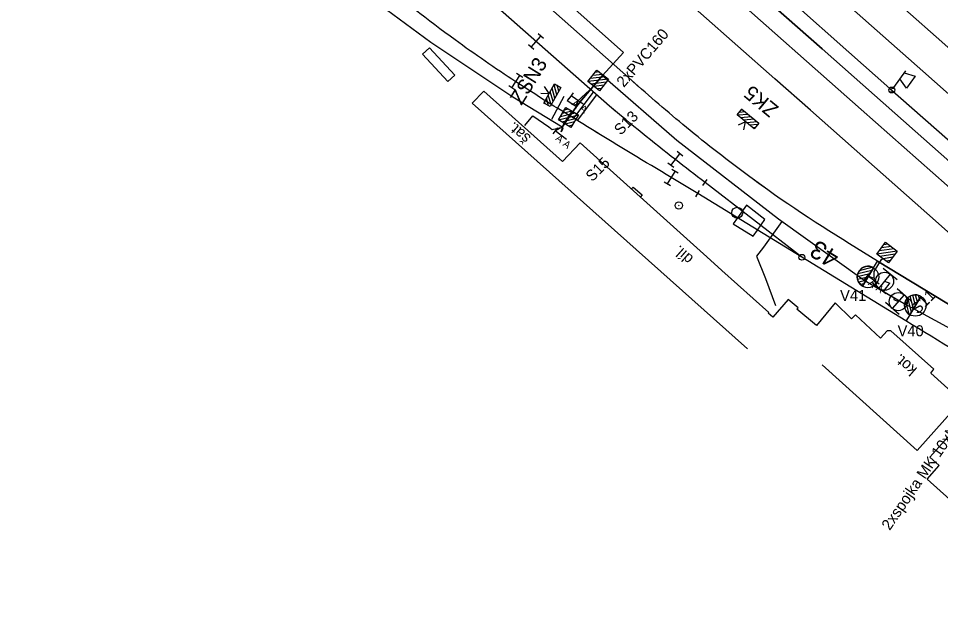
# Model space of a CAD drawing. Extents: x -496570 to -495506, y -1089156 to -1088046.
# Drawn here: x -496392.9 to -496267.2, y -1088434 to -1088354.3 of the extents above; entities that cross this region are included whole.
import ezdxf

# ---------------------------------------------------------------- set-up
doc = ezdxf.new("R2010")
doc.units = 0
for name, color, linetype in [('11', 7, 'Continuous'), ('14', 7, 'Continuous'), ('15', 7, 'Continuous'), ('20', 7, 'Continuous'), ('27', 7, 'Continuous'), ('39', 7, 'Continuous'), ('49', 7, 'Continuous'), ('54', 7, 'Continuous'), ('PŘÍSTUPOVÉ_CESTY', 7, 'Continuous'), ('PŮVODNÍ_NÁVRH', 7, 'Continuous'), ('SEE', 7, 'Continuous')]:
    doc.layers.add(name, color=color, linetype=linetype)

msp = doc.modelspace()

# ---------------------------------------------------------------- linework, layer by layer
at = {"layer": '11'}
for p, q in [((-496317.221, -1088367.889), (-496314.545, -1088364.306)), ((-496316.708, -1088368.205), (-496314.093, -1088364.705)), ((-496302.846, -1088379.821), (-496302.92, -1088379.755))]:
    msp.add_line(p, q, dxfattribs=at)
for centre, radius in [((-496302.883, -1088379.788), 0.5), ((-496294.929, -1088380.778), 0.75)]:
    msp.add_circle(centre, radius, dxfattribs=at)
at = {"layer": '14'}
for points in [[(-496500.326, -1088150.883), (-496478.319, -1088170.391), (-496459.205, -1088187.309), (-496440.603, -1088203.768), (-496419.398, -1088222.532), (-496401.337, -1088238.524), (-496381.863, -1088255.763), (-496363.496, -1088272.022), (-496344.908, -1088288.479), (-496325.602, -1088305.577), (-496305.115, -1088323.698), (-496285.279, -1088341.274), (-496267.778, -1088356.78), (-496248.642, -1088373.733), (-496220.391, -1088398.759), (-496201.351, -1088415.62), (-496182.974, -1088431.889), (-496164.259, -1088448.462), (-496145.687, -1088464.902), (-496132.984, -1088476.226), (-496115.09, -1088492.058), (-496092.682, -1088511.89), (-496073.961, -1088528.378)], [(-496111.45, -1088501.61), (-496112.796, -1088500.414), (-496116.847, -1088496.777), (-496137.726, -1088478.277), (-496158.004, -1088460.314), (-496179.39, -1088441.364), (-496198.571, -1088424.361), (-496223.52, -1088402.267), (-496247.329, -1088381.198), (-496269.626, -1088361.454), (-496288.304, -1088344.927), (-496319.947, -1088316.905), (-496344.485, -1088295.207), (-496348.139, -1088291.966), (-496366.841, -1088275.405), (-496385.169, -1088259.187), (-496404.395, -1088242.153), (-496422.154, -1088226.434), (-496443.818, -1088207.26), (-496462.548, -1088190.678), (-496481.576, -1088173.849), (-496503.417, -1088154.088)], [(-496465.102, -1088201.03), (-496456.086, -1088209.031), (-496439.8, -1088223.453), (-496418.031, -1088242.716), (-496400.164, -1088258.552), (-496382.525, -1088274.174), (-496378.001, -1088278.141), (-496364.605, -1088290.03), (-496358.266, -1088295.605), (-496338.75, -1088312.899), (-496318.462, -1088330.866), (-496297.237, -1088349.647), (-496278.02, -1088366.672), (-496252.626, -1088389.158), (-496233.92, -1088405.779), (-496222.755, -1088415.674), (-496210.969, -1088426.126), (-496208.778, -1088428.033)], [(-496238.055, -1088408.352), (-496252.739, -1088395.349), (-496269.088, -1088380.829), (-496284.933, -1088366.798), (-496289.774, -1088362.518), (-496304.914, -1088349.103), (-496331.751, -1088325.354), (-496382.404, -1088280.635)], [(-496312.364, -1088366.234), (-496339.426, -1088342.308), (-496363.327, -1088321.131), (-496384.97, -1088301.986), (-496397.177, -1088291.214)], [(-496309.356, -1088362.702), (-496336.13, -1088338.96), (-496360.078, -1088317.72), (-496381.817, -1088298.451), (-496389.608, -1088291.56)], [(-496286.111, -1088386.854), (-496299.315, -1088376.648)], [(-496271.935, -1088395.519), (-496286.111, -1088386.854), (-496300.313, -1088378.173)], [(-496225.685, -1088419.311), (-496239.228, -1088409.789), (-496247.333, -1088404.627), (-496261.601, -1088395.991), (-496275.815, -1088387.388)]]:
    msp.add_lwpolyline(points, dxfattribs=at)
for points in [[(-496300.313, -1088378.173), (-496303.924, -1088375.986), (-496314.684, -1088369.445), (-496325.128, -1088362.908), (-496333.397, -1088357.203), (-496344.314, -1088348.841)], [(-496275.815, -1088387.388), (-496290.743, -1088377.667), (-496293.191, -1088375.882), (-496301.865, -1088369.14), (-496309.356, -1088362.702)], [(-496299.315, -1088376.648), (-496303.364, -1088373.532), (-496312.364, -1088366.234)], [(-496239.518, -1088416.014), (-496251.238, -1088408.214), (-496258.061, -1088403.984), (-496271.935, -1088395.519)]]:
    msp.add_spline(points, degree=3, dxfattribs=at)
at = {"layer": '15'}
for p, q in [((-496321.328, -1088357.025), (-496322.076, -1088356.362)), ((-496323.028, -1088358.191), (-496321.702, -1088356.693)), ((-496322.654, -1088358.522), (-496323.402, -1088357.859)), ((-496325.667, -1088363.751), (-496324.589, -1088362.065)), ((-496324.168, -1088362.335), (-496325.01, -1088361.796)), ((-496312.479, -1088362.554), (-496315.287, -1088362.893)), ((-496312.896, -1088362.227), (-496314.96, -1088362.476)), ((-496313.313, -1088361.899), (-496314.632, -1088362.058)), ((-496313.73, -1088361.572), (-496314.305, -1088361.641)), ((-496325.246, -1088364.02), (-496326.088, -1088363.481)), ((-496312.806, -1088362.971), (-496314.87, -1088363.22)), ((-496313.134, -1088363.389), (-496314.452, -1088363.548)), ((-496313.461, -1088363.806), (-496314.035, -1088363.875)), ((-496319.315, -1088368.123), (-496316.572, -1088367.433)), ((-496319.043, -1088367.669), (-496317.027, -1088367.161)), ((-496318.77, -1088367.213), (-496317.482, -1088366.889)), ((-496318.498, -1088366.758), (-496317.937, -1088366.617)), ((-496318.86, -1088368.395), (-496316.844, -1088367.888)), ((-496318.404, -1088368.668), (-496317.116, -1088368.344)), ((-496317.949, -1088368.94), (-496317.388, -1088368.799)), ((-496302.352, -1088373.057), (-496303.136, -1088372.437)), ((-496303.984, -1088374.316), (-496302.744, -1088372.748)), ((-496304.439, -1088376.843), (-496303.409, -1088375.129)), ((-496303.592, -1088374.627), (-496304.376, -1088374.007)), ((-496302.981, -1088375.387), (-496303.837, -1088374.871)), ((-496304.011, -1088377.101), (-496304.867, -1088376.585)), ((-496274.369, -1088385.053), (-496274.942, -1088385.137)), ((-496273.093, -1088386.003), (-496275.892, -1088386.413)), ((-496273.518, -1088385.687), (-496275.575, -1088385.988)), ((-496273.41, -1088386.429), (-496275.467, -1088386.729)), ((-496273.944, -1088385.37), (-496275.258, -1088385.562)), ((-496273.727, -1088386.854), (-496275.041, -1088387.046)), ((-496274.044, -1088387.279), (-496274.616, -1088387.363)), ((-496273.098, -1088389.923), (-496275.017, -1088388.378)), ((-496274.643, -1088391.842), (-496276.562, -1088390.297)), ((-496274.058, -1088389.15), (-496275.602, -1088391.07)), ((-496271.232, -1088392.777), (-496273.093, -1088391.162)), ((-496272.162, -1088391.97), (-496273.778, -1088393.83)), ((-496272.847, -1088394.638), (-496274.708, -1088393.023))]:
    msp.add_line(p, q, dxfattribs=at)
for points in [[(-496313.713, -1088364.127), (-496315.287, -1088362.893), (-496314.052, -1088361.319), (-496312.479, -1088362.554)], [(-496313.713, -1088364.127), (-496315.287, -1088362.893), (-496314.052, -1088361.319), (-496312.479, -1088362.554)], [(-496318.288, -1088366.407), (-496316.572, -1088367.433), (-496317.598, -1088369.15), (-496319.315, -1088368.123)], [(-496318.288, -1088366.407), (-496316.572, -1088367.433), (-496317.598, -1088369.15), (-496319.315, -1088368.123)], [(-496274.288, -1088387.607), (-496275.892, -1088386.413), (-496274.697, -1088384.809), (-496273.093, -1088386.003)], [(-496274.288, -1088387.607), (-496275.892, -1088386.413), (-496274.697, -1088384.809), (-496273.093, -1088386.003)]]:
    msp.add_lwpolyline(points, close=True, dxfattribs=at)
for points in [[(-496313.713, -1088364.127), (-496315.287, -1088362.893), (-496314.052, -1088361.319), (-496312.479, -1088362.554), (-496313.713, -1088364.127)], [(-496313.713, -1088364.127), (-496315.287, -1088362.893), (-496314.052, -1088361.319), (-496312.479, -1088362.554), (-496313.713, -1088364.127)], [(-496318.288, -1088366.407), (-496316.572, -1088367.433), (-496317.598, -1088369.15), (-496319.315, -1088368.123), (-496318.288, -1088366.407)], [(-496318.288, -1088366.407), (-496316.572, -1088367.433), (-496317.598, -1088369.15), (-496319.315, -1088368.123), (-496318.288, -1088366.407)], [(-496274.288, -1088387.607), (-496275.892, -1088386.413), (-496274.697, -1088384.809), (-496273.093, -1088386.003), (-496274.288, -1088387.607)], [(-496274.288, -1088387.607), (-496275.892, -1088386.413), (-496274.697, -1088384.809), (-496273.093, -1088386.003), (-496274.288, -1088387.607)]]:
    msp.add_lwpolyline(points, dxfattribs=at)
for centre in [(-496274.832, -1088390.115), (-496272.972, -1088392.905)]:
    msp.add_circle(centre, 1.232, dxfattribs=at)
at = {"layer": '20'}
for p, q in [((-496317.297, -1088364.43), (-496317.867, -1088365.252)), ((-496315.955, -1088365.97), (-496317.582, -1088364.841)), ((-496319.451, -1088369.2), (-496320.063, -1088369.99)), ((-496318.191, -1088370.806), (-496319.757, -1088369.595)), ((-496276.892, -1088388.957), (-496277.462, -1088389.779)), ((-496275.55, -1088390.497), (-496277.177, -1088389.368))]:
    msp.add_line(p, q, dxfattribs=at)
at = {"layer": '27'}
for p, q in [((-496299.62, -1088377.044), (-496299.01, -1088376.252)), ((-496300.574, -1088378.599), (-496300.052, -1088377.747)), ((-496276.34, -1088388.272), (-496275.815, -1088387.388)), ((-496276.557, -1088388.638), (-496278.495, -1088389.128)), ((-496276.441, -1088388.222), (-496278.281, -1088388.687)), ((-496277.84, -1088390.786), (-496276.341, -1088388.272)), ((-496276.34, -1088388.273), (-496277.84, -1088390.786)), ((-496276.341, -1088388.272), (-496276.34, -1088388.273)), ((-496276.828, -1088389.093), (-496278.552, -1088389.528)), ((-496277.101, -1088389.549), (-496278.502, -1088389.903)), ((-496277.374, -1088390.004), (-496278.357, -1088390.253)), ((-496277.645, -1088390.46), (-496278.108, -1088390.577)), ((-496271.493, -1088394.623), (-496271.949, -1088392.78)), ((-496271.181, -1088394.324), (-496271.66, -1088392.384)), ((-496269.888, -1088392.182), (-496271.402, -1088394.687)), ((-496271.401, -1088394.688), (-496269.888, -1088392.182)), ((-496270.907, -1088393.87), (-496271.333, -1088392.145)), ((-496270.633, -1088393.415), (-496270.98, -1088392.013)), ((-496270.359, -1088392.962), (-496270.603, -1088391.975)), ((-496270.084, -1088392.507), (-496270.199, -1088392.044)), ((-496271.401, -1088394.688), (-496271.935, -1088395.567)), ((-496271.402, -1088394.687), (-496271.401, -1088394.688))]:
    msp.add_line(p, q, dxfattribs=at)
for points in [[(-496286.111, -1088386.854), (-496299.315, -1088376.648)], [(-496271.935, -1088395.519), (-496286.111, -1088386.854), (-496300.313, -1088378.173)], [(-496275.815, -1088387.388), (-496261.601, -1088395.991), (-496247.333, -1088404.627)]]:
    msp.add_lwpolyline(points, dxfattribs=at)
for centre, radius in [((-496286.111, -1088386.854), 0.4), ((-496277.095, -1088389.536), 1.462), ((-496270.642, -1088393.427), 1.462)]:
    msp.add_circle(centre, radius, dxfattribs=at)
for centre, start, end in [((-496277.09, -1088389.53), 59.19792, 239.15877), ((-496270.644, -1088393.435), 58.89197, 238.85282)]:
    msp.add_arc(centre, 1.464, start, end, dxfattribs=at)
at = {"layer": '39'}
for p, q in [((-496333.442, -1088362.019), (-496336.901, -1088358.276)), ((-496334.389, -1088362.895), (-496333.442, -1088362.019))]:
    msp.add_line(p, q, dxfattribs=at)
for points in [[(-496336.901, -1088358.276), (-496337.848, -1088359.152), (-496334.389, -1088362.895)], [(-496270.398, -1088413.199), (-496264.319, -1088406.454), (-496268.54, -1088402.65), (-496268.109, -1088402.133), (-496273.976, -1088396.875), (-496274.471, -1088396.883), (-496275.403, -1088397.88), (-496278.797, -1088394.71), (-496279.327, -1088395.258), (-496281.591, -1088393.068), (-496284.121, -1088396.139), (-496286.79, -1088393.94), (-496286.631, -1088393.747), (-496287.972, -1088392.629), (-496290.06, -1088395.029), (-496290.69, -1088394.461), (-496290.624, -1088394.387), (-496297.006, -1088388.637), (-496299.062, -1088386.784), (-496316.329, -1088371.229), (-496318.738, -1088373.773), (-496329.498, -1088364.171), (-496331.093, -1088365.84)], [(-496331.093, -1088365.84), (-496293.543, -1088399.349)], [(-496309.349, -1088377.517), (-496309.134, -1088377.279), (-496307.894, -1088378.354), (-496308.13, -1088378.616)], [(-496270.398, -1088413.199), (-496283.344, -1088401.532)], [(-496261.958, -1088423.433), (-496269.031, -1088417.102), (-496267.367, -1088415.244), (-496268.641, -1088414.103), (-496263.772, -1088408.664), (-496244.63, -1088425.633), (-496246.068, -1088427.269), (-496244.762, -1088428.416), (-496247.293, -1088431.247), (-496248.615, -1088430.059), (-496249.511, -1088431.056), (-496260.279, -1088421.534), (-496261.958, -1088423.433)]]:
    msp.add_lwpolyline(points, dxfattribs=at)
at = {"layer": '49'}
for p, q in [((-496308.465, -1088363.496), (-496309.356, -1088362.702)), ((-496311.447, -1088367.014), (-496312.364, -1088366.234)), ((-496313.827, -1088369.963), (-496314.684, -1088369.445))]:
    msp.add_line(p, q, dxfattribs=at)
for points in [[(-496290.743, -1088377.667), (-496293.191, -1088375.882)], [(-496292.749, -1088383.951), (-496292.171, -1088383.138), (-496291.15, -1088381.699), (-496293.657, -1088379.762), (-496294.884, -1088381.49), (-496295.462, -1088382.303), (-496292.749, -1088383.951)]]:
    msp.add_lwpolyline(points, dxfattribs=at)
at = {"layer": '54'}
for p, q in [((-496318.803, -1088369.122), (-496319.757, -1088369.595)), ((-496276.23, -1088389.69), (-496276.08, -1088390.07))]:
    msp.add_line(p, q, dxfattribs=at)
for points in [[(-496433.49, -1088225.14), (-496433.04, -1088225.62), (-496416.56, -1088240.21), (-496398.63, -1088256.07), (-496371.25, -1088279.76), (-496353.65, -1088295.93), (-496335.7, -1088311.84), (-496319.23, -1088326.41), (-496317.95, -1088325.09), (-496317.88, -1088325.11), (-496309.26, -1088332.67), (-496302.22, -1088338.89), (-496294.56, -1088345.71), (-496287.4, -1088352.05), (-496279.7, -1088358.86), (-496274.1, -1088363.82), (-496264.77, -1088372.06), (-496257.24, -1088378.7), (-496256.98, -1088378.95)], [(-496252.528, -1088385.701), (-496270.673, -1088369.666), (-496283.364, -1088358.425), (-496295.304, -1088347.848), (-496296.295, -1088345.046), (-496298.05, -1088343.439), (-496300.521, -1088343.235), (-496321.648, -1088324.528), (-496337.881, -1088310.154), (-496338.669, -1088307.53), (-496339.456, -1088306.765), (-496340.38, -1088305.964), (-496342.857, -1088305.764), (-496354.51, -1088295.443), (-496365.46, -1088285.379), (-496371.11, -1088280.23)], [(-496371.11, -1088280.23), (-496365.46, -1088285.379), (-496354.51, -1088295.443), (-496342.857, -1088305.764), (-496340.38, -1088305.964), (-496338.669, -1088307.53), (-496337.881, -1088310.154), (-496321.648, -1088324.528), (-496300.521, -1088343.235), (-496298.05, -1088343.439), (-496296.295, -1088345.046), (-496295.304, -1088347.848), (-496283.364, -1088358.425), (-496270.673, -1088369.666), (-496252.528, -1088385.701), (-496249.196, -1088385.882), (-496241.162, -1088393.056), (-496240.55, -1088394.77)], [(-496252.528, -1088385.701), (-496270.673, -1088369.666), (-496283.364, -1088358.425), (-496295.304, -1088347.848), (-496296.295, -1088345.046), (-496298.05, -1088343.439), (-496300.521, -1088343.235), (-496321.648, -1088324.528), (-496337.881, -1088310.154), (-496338.669, -1088307.53), (-496339.53, -1088306.668), (-496335.82, -1088302.83), (-496323.03, -1088287.1), (-496324.84, -1088284.59)], [(-496386.48, -1088299.69), (-496385.45, -1088298.5), (-496385.32, -1088298.53), (-496384.38, -1088299.3), (-496383.57, -1088299.87), (-496383.33, -1088299.55), (-496381.5, -1088297.23), (-496380.72, -1088296.56), (-496376.63, -1088300.17), (-496376.36, -1088300.28), (-496376.131, -1088300.534), (-496363.656, -1088311.517), (-496348.938, -1088324.637), (-496332.315, -1088339.298), (-496318.718, -1088351.516), (-496310.422, -1088358.908), (-496313.3, -1088362.068), (-496303.169, -1088370.868), (-496289.313, -1088381.611), (-496277.617, -1088389.974), (-496274.964, -1088391.538), (-496273.52, -1088392.39), (-496272.174, -1088393.151), (-496263.798, -1088397.711)], [(-496313.3, -1088362.068), (-496316.165, -1088365.411), (-496316.842, -1088366.293), (-496318.803, -1088369.122), (-496325.528, -1088365.013), (-496336.692, -1088357.548), (-496347.943, -1088349.238), (-496353.534, -1088343.739), (-496361.445, -1088336.23), (-496368.727, -1088330.913), (-496367.259, -1088329.015)], [(-496317.582, -1088364.841), (-496318.132, -1088365.472), (-496316.842, -1088366.293), (-496316.74, -1088365.69), (-496316.74, -1088365.6), (-496314.5, -1088363.51)], [(-496318.803, -1088369.122), (-496318.72, -1088369.28), (-496318.91, -1088369.68), (-496318.95, -1088369.75), (-496318.58, -1088368.65), (-496317.43, -1088366.92)], [(-496277.617, -1088389.974), (-496277.177, -1088389.368), (-496276.23, -1088389.69), (-496276.24, -1088388.78), (-496275.27, -1088387.14), (-496275.09, -1088387.01)], [(-496274.83, -1088390.11), (-496274.12, -1088390.37), (-496274.25, -1088390.53), (-496274.74, -1088391.14), (-496274.964, -1088391.538)], [(-496273.52, -1088392.39), (-496273.56, -1088392.59), (-496272.97, -1088392.9)]]:
    msp.add_lwpolyline(points, dxfattribs=at)
at = {"layer": 'PŘÍSTUPOVÉ_CESTY'}
for p, q in [((-496271.978, -1088361.44), (-496273.632, -1088363.694)), ((-496271.836, -1088363.778), (-496272.748, -1088362.487)), ((-496272.156, -1088361.681), (-496270.651, -1088362.167)), ((-496270.651, -1088362.167), (-496271.836, -1088363.778)), ((-496319.787, -1088365.134), (-496320.166, -1088363.772)), ((-496319.526, -1088364.672), (-496319.905, -1088363.309)), ((-496319.265, -1088364.21), (-496319.493, -1088363.393)), ((-496319.005, -1088363.748), (-496319.031, -1088363.653)), ((-496274.225, -1088363.891), (-496273.537, -1088363.786)), ((-496320.664, -1088366.176), (-496320.948, -1088365.157)), ((-496320.308, -1088366.057), (-496320.687, -1088364.695)), ((-496320.047, -1088365.596), (-496320.427, -1088364.233)), ((-496274.156, -1088364.286), (-496273.482, -1088364.183)), ((-496321.126, -1088365.916), (-496321.209, -1088365.619)), ((-496293.425, -1088367.356), (-496294.833, -1088367.488)), ((-496293.833, -1088367.018), (-496294.678, -1088367.097)), ((-496293.016, -1088367.695), (-496294.424, -1088367.827)), ((-496294.241, -1088366.679), (-496294.339, -1088366.689)), ((-496292.608, -1088368.033), (-496294.016, -1088368.165)), ((-496292.2, -1088368.371), (-496293.608, -1088368.503)), ((-496292.146, -1088368.743), (-496293.199, -1088368.842)), ((-496292.484, -1088369.151), (-496292.791, -1088369.18))]:
    msp.add_line(p, q, dxfattribs=at)
for points in [[(-496321.695, -1088364.446), (-496320.578, -1088364.502), (-496321.204, -1088363.575)], [(-496321.316, -1088365.809), (-496319.841, -1088363.196), (-496318.97, -1088363.687), (-496320.445, -1088366.3), (-496321.316, -1088365.809)], [(-496292.623, -1088369.319), (-496294.933, -1088367.405), (-496294.295, -1088366.635), (-496291.985, -1088368.549), (-496292.623, -1088369.319)], [(-496294.031, -1088369.451), (-496293.778, -1088368.362), (-496294.801, -1088368.813)]]:
    msp.add_lwpolyline(points, dxfattribs=at)
for points in [[(-496321.316, -1088365.809), (-496319.841, -1088363.196), (-496318.97, -1088363.687), (-496320.445, -1088366.3)], [(-496292.623, -1088369.319), (-496294.933, -1088367.405), (-496294.295, -1088366.635), (-496291.985, -1088368.549)]]:
    msp.add_lwpolyline(points, close=True, dxfattribs=at)
msp.add_circle((-496273.85, -1088364.03), 0.401, dxfattribs=at)
msp.add_circle((-496273.85, -1088364.03), 0.401, dxfattribs=at)
at = {"layer": 'PŮVODNÍ_NÁVRH'}
msp.add_line((-496320.193, -1088368.025), (-496318.511, -1088364.863), dxfattribs=at)
for points in [[(-496248.182, -1088386.654), (-496249.196, -1088385.882), (-496252.528, -1088385.701), (-496270.673, -1088369.666), (-496283.364, -1088358.425), (-496295.304, -1088347.848), (-496296.295, -1088345.046), (-496298.05, -1088343.439), (-496300.521, -1088343.235), (-496321.648, -1088324.528), (-496337.881, -1088310.154), (-496338.669, -1088307.53)], [(-496318.803, -1088369.122), (-496316.842, -1088366.293), (-496313.3, -1088362.068), (-496310.422, -1088358.908)]]:
    msp.add_lwpolyline(points, dxfattribs=at)
at = {"layer": 'SEE'}
for points in [[(-496371.11, -1088280.23), (-496365.46, -1088285.379), (-496354.51, -1088295.443), (-496342.857, -1088305.764), (-496340.38, -1088305.964), (-496338.669, -1088307.53), (-496337.881, -1088310.154), (-496321.648, -1088324.528), (-496300.521, -1088343.235), (-496298.05, -1088343.439), (-496296.295, -1088345.046), (-496295.304, -1088347.848), (-496283.364, -1088358.425), (-496270.673, -1088369.666), (-496252.528, -1088385.701)], [(-496371.11, -1088280.23), (-496365.46, -1088285.379), (-496354.51, -1088295.443), (-496342.857, -1088305.764), (-496340.38, -1088305.964), (-496338.669, -1088307.53), (-496337.881, -1088310.154), (-496321.648, -1088324.528), (-496300.521, -1088343.235), (-496298.05, -1088343.439), (-496296.295, -1088345.046), (-496295.304, -1088347.848), (-496283.364, -1088358.425), (-496270.673, -1088369.666), (-496252.528, -1088385.701)], [(-496323.87, -1088368.88), (-496322.81, -1088367.54), (-496320.63, -1088369.08), (-496320.14, -1088369.4), (-496318.803, -1088369.122), (-496316.842, -1088366.293), (-496316.165, -1088365.411), (-496313.3, -1088362.068), (-496303.169, -1088370.868), (-496289.313, -1088381.611), (-496277.617, -1088389.974), (-496272.174, -1088393.151), (-496263.798, -1088397.711)], [(-496288.833, -1088381.954), (-496291.34, -1088385.46), (-496292.29, -1088386.69), (-496291.06, -1088389.74), (-496289.72, -1088393.45)]]:
    msp.add_lwpolyline(points, dxfattribs=at)

# ---------------------------------------------------------------- texts
at = {"layer": '15'}
for s, p in [('V41', (-496280.901, -1088392.812)), ('V40', (-496273.058, -1088397.628))]:
    msp.add_text(s, height=1.5, dxfattribs=at).set_placement(p)
at = {"layer": '20'}
for s, height, rotation, p in [('  A A', 1, 325.23688, (-496318.173, -1088365.617)), ('S13', 1.5, 44.94179, (-496310.827, -1088370.3)), ('  A A', 1, 322.27745, (-496320.387, -1088370.339)), ('S15', 1.5, 44.94179, (-496314.694, -1088376.625)), ('  A A', 1, 325.23688, (-496277.768, -1088390.144)), ('S11', 1.5, 44.94179, (-496270.296, -1088394.701))]:
    msp.add_text(s, height=height, rotation=rotation, dxfattribs=at).set_placement(p)
at = {"layer": '27'}
msp.add_text('43', height=2.5, rotation=148.56488, dxfattribs=at).set_placement((-496280.808, -1088386.334))
at = {"layer": '39'}
for s, p in [('šat.', (-496322.964, -1088370.416)), ('díl.', (-496300.801, -1088386.871)), ('kot.', (-496270.284, -1088402.046))]:
    msp.add_text(s, height=1.5, rotation=138.51409, dxfattribs=at).set_placement(p)
at = {"layer": '54'}
msp.add_text('2xPVC160', height=1.5, rotation=49.48633, dxfattribs=at).set_placement((-496310.389, -1088363.763))
at = {"layer": 'PŘÍSTUPOVÉ_CESTY'}
for s, rotation, p in [('ZSN3', 58.23944, (-496324.342, -1088366.221)), ('ZK5', 140.34568, (-496289.161, -1088366.387))]:
    msp.add_text(s, height=2, rotation=rotation, dxfattribs=at).set_placement(p)
at = {"layer": 'SEE'}
msp.add_text('2xspojka MK 10xNx0,8 a 25xNx0,6', height=1.5, rotation=55.62336, dxfattribs=at).set_placement((-496274.124, -1088424.199))

doc.saveas('drawing.dxf')
